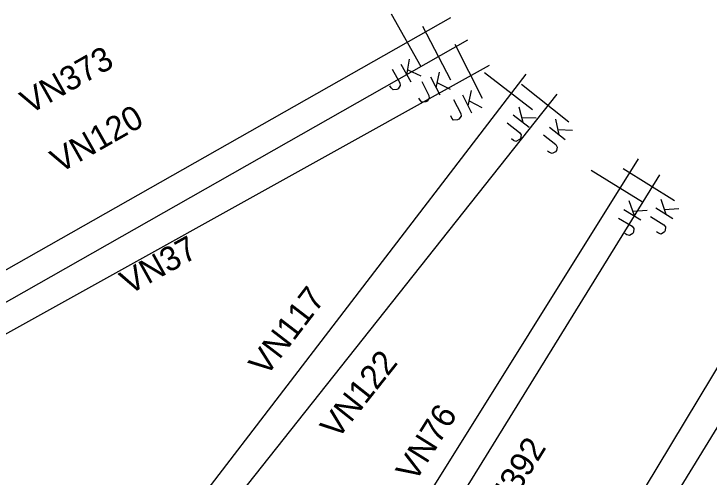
# Model space of a CAD drawing. Extents: x -540340 to -537226, y -1183949 to -1180375.
# Drawn here: x -537543.05 to -537514.32, y -1180653.13 to -1180634 of the extents above; entities that cross this region are included whole.
import ezdxf

# ---------------------------------------------------------------- set-up
doc = ezdxf.new("R2010")
doc.units = 0
for name, color, linetype in [('Vrstva 1', 7, 'Continuous'), ('Vrstva 18', 7, 'Continuous'), ('Vrstva 3', 7, 'Continuous')]:
    doc.layers.add(name, color=color, linetype=linetype)

msp = doc.modelspace()

# ---------------------------------------------------------------- linework, layer by layer
at = {"layer": 'Vrstva 1'}
for points in [[(-537549.422, -1180647.98), (-537524.988, -1180634.15)], [(-537548.921, -1180649.045), (-537524.287, -1180635.072)], [(-537548.494, -1180650.052), (-537523.399, -1180636.113)], [(-537537.553, -1180656.912), (-537521.871, -1180636.493)], [(-537536.659, -1180657.565), (-537520.59, -1180637.312)], [(-537517.243, -1180639.978), (-537530.88, -1180661.777)], [(-537516.363, -1180640.64), (-537529.897, -1180662.526), (-537531.994, -1180665.405)], [(-537524.622, -1180666.267), (-537524.208, -1180665.581), (-537511.413, -1180644.384)], [(-537523.685, -1180666.914), (-537523.331, -1180666.336), (-537510.283, -1180645.074)]]:
    msp.add_lwpolyline(points, dxfattribs=at)
at = {"layer": 'Vrstva 18'}
for points in [[(-537527.457, -1180634), (-537526.231, -1180636.178)], [(-537526.165, -1180634.512), (-537525.008, -1180636.728)], [(-537524.826, -1180635.253), (-537523.691, -1180637.48)], [(-537526.805, -1180636.524), (-537526.696, -1180635.875)], [(-537527.416, -1180636.281), (-537527.098, -1180636.847)], [(-537527.056, -1180636.078), (-537526.65, -1180636.798)], [(-537526.767, -1180636.31), (-537526.23, -1180636.562)], [(-537525.83, -1180636.602), (-537525.447, -1180637.335)], [(-537525.593, -1180637.056), (-537525.463, -1180636.41)], [(-537523.598, -1180636.419), (-537521.615, -1180637.942)], [(-537527.098, -1180636.847), (-537527.079, -1180636.96)], [(-537526.196, -1180636.793), (-537525.896, -1180637.369)], [(-537525.548, -1180636.843), (-537525.019, -1180637.112)], [(-537522.068, -1180636.899), (-537520.107, -1180638.451)], [(-537527.458, -1180637.049), (-537527.506, -1180636.964)], [(-537527.379, -1180637.129), (-537527.458, -1180637.049)], [(-537527.217, -1180637.117), (-537527.379, -1180637.129)], [(-537527.165, -1180637.088), (-537527.217, -1180637.117)], [(-537527.079, -1180636.96), (-537527.165, -1180637.088)], [(-537524.278, -1180637.802), (-537524.143, -1180637.158)], [(-537526.262, -1180637.56), (-537526.307, -1180637.473)], [(-537525.896, -1180637.369), (-537525.88, -1180637.483)], [(-537524.511, -1180637.346), (-537524.135, -1180638.082)], [(-537526.186, -1180637.643), (-537526.262, -1180637.56)], [(-537526.023, -1180637.635), (-537526.186, -1180637.643)], [(-537525.971, -1180637.608), (-537526.023, -1180637.635)], [(-537525.88, -1180637.483), (-537525.971, -1180637.608)], [(-537524.879, -1180637.533), (-537524.584, -1180638.112)], [(-537524.232, -1180637.59), (-537523.706, -1180637.863)], [(-537522.007, -1180638.485), (-537522.162, -1180637.845)], [(-537524.952, -1180638.3), (-537524.997, -1180638.212)], [(-537524.877, -1180638.383), (-537524.952, -1180638.3)], [(-537524.57, -1180638.227), (-537524.661, -1180638.351)], [(-537524.584, -1180638.112), (-537524.57, -1180638.227)], [(-537522.413, -1180638.173), (-537521.757, -1180638.677)], [(-537522.056, -1180638.274), (-537521.464, -1180638.294)], [(-537524.714, -1180638.377), (-537524.877, -1180638.383)], [(-537524.661, -1180638.351), (-537524.714, -1180638.377)], [(-537522.665, -1180638.501), (-537522.15, -1180638.896)], [(-537520.507, -1180638.988), (-537520.652, -1180638.346)], [(-537522.15, -1180638.896), (-537522.088, -1180638.994)], [(-537520.909, -1180638.67), (-537520.26, -1180639.183)], [(-537520.553, -1180638.776), (-537519.961, -1180638.805)], [(-537522.402, -1180639.224), (-537522.48, -1180639.164)], [(-537522.153, -1180639.192), (-537522.298, -1180639.267)], [(-537522.117, -1180639.145), (-537522.153, -1180639.192)], [(-537522.088, -1180638.994), (-537522.117, -1180639.145)], [(-537521.165, -1180638.994), (-537520.656, -1180639.398)], [(-537522.298, -1180639.267), (-537522.402, -1180639.224)], [(-537520.656, -1180639.398), (-537520.595, -1180639.496)], [(-537520.912, -1180639.722), (-537520.989, -1180639.661)], [(-537520.809, -1180639.766), (-537520.912, -1180639.722)], [(-537520.663, -1180639.693), (-537520.809, -1180639.766)], [(-537520.627, -1180639.646), (-537520.663, -1180639.693)], [(-537520.595, -1180639.496), (-537520.627, -1180639.646)], [(-537519.196, -1180640.454), (-537517.067, -1180641.764)], [(-537517.863, -1180640.377), (-537515.745, -1180641.705)], [(-537517.401, -1180642.345), (-537517.621, -1180641.724)], [(-537516.083, -1180642.282), (-537516.298, -1180641.66)], [(-537516.517, -1180642.01), (-537515.816, -1180642.449)], [(-537516.152, -1180642.077), (-537515.56, -1180642.041)], [(-537517.837, -1180642.076), (-537517.133, -1180642.51)], [(-537517.472, -1180642.139), (-537516.88, -1180642.099)], [(-537518.054, -1180642.428), (-537517.501, -1180642.769)], [(-537516.737, -1180642.361), (-537516.186, -1180642.706)], [(-537517.501, -1180642.769), (-537517.429, -1180642.859)], [(-537517.429, -1180642.859), (-537517.443, -1180643.012)], [(-537516.186, -1180642.706), (-537516.115, -1180642.797)], [(-537516.115, -1180642.797), (-537516.13, -1180642.95)], [(-537517.717, -1180643.121), (-537517.801, -1180643.069)], [(-537517.61, -1180643.153), (-537517.717, -1180643.121)], [(-537517.474, -1180643.063), (-537517.61, -1180643.153)], [(-537517.443, -1180643.012), (-537517.474, -1180643.063)], [(-537516.405, -1180643.056), (-537516.489, -1180643.004)], [(-537516.298, -1180643.089), (-537516.405, -1180643.056)], [(-537516.161, -1180643), (-537516.298, -1180643.089)], [(-537516.13, -1180642.95), (-537516.161, -1180643)]]:
    msp.add_lwpolyline(points, dxfattribs=at)

# ---------------------------------------------------------------- texts
at = {"layer": 'Vrstva 3'}
for s, rotation, p in [('VN373', 29.51, (-537542.409, -1180638.163)), ('VN120', 29.563, (-537541.167, -1180640.595)), ('VN37', 29.051, (-537538.296, -1180645.614)), ('VN117', 52.475, (-537532.625, -1180649.014)), ('VN122', 51.571, (-537529.684, -1180651.613)), ('VN76', 57.971, (-537526.471, -1180653.375)), ('VN392', 58.268, (-537523.17, -1180655.377))]:
    msp.add_text(s, height=1, rotation=rotation, dxfattribs=at).set_placement(p)

doc.saveas('drawing.dxf')
